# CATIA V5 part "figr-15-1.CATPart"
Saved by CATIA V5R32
Part number: Part1
Bounding box of the stored display mesh (mm): x -92.657 to 112.488, y -68.408 to 38.341, z -24 to 61.972
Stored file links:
  D:\PROJECTS\Project 2022\CATIA V5 6R 2022\Resources\Part Files\c15_catia_v5_6r2022_prt\figr-15-1.CATPart
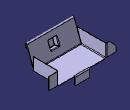
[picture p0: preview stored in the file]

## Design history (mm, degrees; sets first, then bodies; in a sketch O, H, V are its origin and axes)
SheetMetalParameters1: Thickness 1, BendRadius 2, KFactor 0.400515 {= log(min(100,max(20*SheetMetalParameters1.BendRadius,SheetMetalParameters1.Thickness)/SheetMetalParameters1.Thickness))/log(100)/2}, ReliefRadialLength 1, ReliefAxialLength 2, WallPerLength 50, MinimumBendRadius 0
Body1 (main body)
  Sketch1 on xy-plane, origin (0, 0, 0), H (1, 0, 0), V (0, 1, 0)
    line L1 (-62.6567, 37.3409) -> (82.4875, 37.3409)
    line L2 (82.4875, 37.3409) -> (82.4875, -38.1848)
    line L3 (82.4875, -38.1848) -> (-62.6567, -38.1848)
    line L4 (-62.6567, -38.1848) -> (-62.6567, 37.3409)
    horizontal: L1 H, L3 H
    vertical: L2 V, L4 V
  Wall1: Thickness 1, Profile Sketch1, OffsetValue 0
  d_NewWallOnEdge1: KFacteur 0.400515 {= log(min(100,max(20*d_NewWallOnEdge1.Radius,SheetMetalParameters1.Thickness)/SheetMetalParameters1.Thickness))/log(100)/2}, NewWallOnEdge_Length 25, NewWallOnEdge_HeightLimitOffset 0, NewWallOnEdge_WidthOffset1 -50, NewWallOnEdge_WidthOffset2 -50, NewWallOnEdge_Angle 90, NewWallOnEdge_BendRadiusValue 2 {= SheetMetalParameters1.BendRadius}, NewWallOnEdge_BendTable SheetMetalParameters1, NewWallOnEdge_Edge edge [face of Wall1 | face of Wall1], NewWallOnEdge_GapValue 0
  d_NewWallOnEdge2: KFacteur 0.400515 {= log(min(100,max(20*d_NewWallOnEdge2.Radius,SheetMetalParameters1.Thickness)/SheetMetalParameters1.Thickness))/log(100)/2}, NewWallOnEdge_Length 40, NewWallOnEdge_HeightLimitOffset 0, NewWallOnEdge_WidthOffset1 0, NewWallOnEdge_WidthOffset2 0, NewWallOnEdge_Angle 90, NewWallOnEdge_BendRadiusValue 2 {= SheetMetalParameters1.BendRadius}, NewWallOnEdge_BendTable SheetMetalParameters1, NewWallOnEdge_Edge edge [face of Wall1 | face of Wall1], NewWallOnEdge_GapValue 0
  d_NewWallOnEdge3: KFacteur 0.400515 {= log(min(100,max(20*d_NewWallOnEdge3.Radius,SheetMetalParameters1.Thickness)/SheetMetalParameters1.Thickness))/log(100)/2}, NewWallOnEdge_Length 30, NewWallOnEdge_HeightLimitOffset 0, NewWallOnEdge_WidthOffset1 0, NewWallOnEdge_WidthOffset2 0, NewWallOnEdge_Angle 90, NewWallOnEdge_BendRadiusValue 2 {= SheetMetalParameters1.BendRadius}, NewWallOnEdge_BendTable SheetMetalParameters1, NewWallOnEdge_Edge edge [face of d_NewWallOnEdge2 | face of d_NewWallOnEdge2], NewWallOnEdge_GapValue 0
  d_NewWallOnEdge4: KFacteur 0.400515 {= log(min(100,max(20*d_NewWallOnEdge4.Radius,SheetMetalParameters1.Thickness)/SheetMetalParameters1.Thickness))/log(100)/2}, NewWallOnEdge_Length 60, NewWallOnEdge_HeightLimitOffset 0, NewWallOnEdge_WidthOffset1 0, NewWallOnEdge_WidthOffset2 0, NewWallOnEdge_Angle 110, NewWallOnEdge_BendRadiusValue 2 {= SheetMetalParameters1.BendRadius}, NewWallOnEdge_BendTable SheetMetalParameters1, NewWallOnEdge_Edge edge [face of Wall1 | face of Wall1], NewWallOnEdge_GapValue 0
  Flange1: Guide edge [face of d_NewWallOnEdge4 | face of d_NewWallOnEdge4], Angle 90, KFacteur 0.400515 {= log(min(100,max(20*Flange1.Radius,SheetMetalParameters1.Thickness)/SheetMetalParameters1.Thickness))/log(100)/2}, Length 10, Radius 2 {= SheetMetalParameters1.BendRadius}
  d_NewWallOnEdge5: KFacteur 0.400515 {= log(min(100,max(20*d_NewWallOnEdge5.Radius,SheetMetalParameters1.Thickness)/SheetMetalParameters1.Thickness))/log(100)/2}, NewWallOnEdge_Length 40, NewWallOnEdge_HeightLimitOffset 0, NewWallOnEdge_WidthLimit2 face of d_NewWallOnEdge4, NewWallOnEdge_WidthOffset1 0, NewWallOnEdge_WidthOffset2 -2, NewWallOnEdge_Angle 90, NewWallOnEdge_WithBend true, NewWallOnEdge_BendRadiusValue 2 {= SheetMetalParameters1.BendRadius}, NewWallOnEdge_BendTable SheetMetalParameters1, NewWallOnEdge_Edge edge [face of Wall1 | face of Wall1], NewWallOnEdge_GapValue 0
  d_NewWallOnEdge6: KFacteur 0.400515 {= log(min(100,max(20*d_NewWallOnEdge6.Radius,SheetMetalParameters1.Thickness)/SheetMetalParameters1.Thickness))/log(100)/2}, NewWallOnEdge_Length 30, NewWallOnEdge_HeightLimitOffset 0, NewWallOnEdge_WidthOffset1 0, NewWallOnEdge_WidthOffset2 0, NewWallOnEdge_Angle 90, NewWallOnEdge_BendRadiusValue 2 {= SheetMetalParameters1.BendRadius}, NewWallOnEdge_BendTable SheetMetalParameters1, NewWallOnEdge_Edge edge [face of d_NewWallOnEdge5 | face of d_NewWallOnEdge5], NewWallOnEdge_GapValue 0
  Chamfer1: ChamferAngle 45, CornerChamferEdges edge [face of d_NewWallOnEdge6 | face of d_NewWallOnEdge6], ChamferLength1 20, ChamferLength2 0.5, ChamferPropagation 1, ChamferReverse false, ChamferType 1
  Corner1: CornerChamferEdges (edge [face of d_NewWallOnEdge1 | face of d_NewWallOnEdge1]; edge [face of d_NewWallOnEdge1 | face of d_NewWallOnEdge1]), CornerRadius 3
  Sketch2 on face of d_NewWallOnEdge4, origin (8.9154, -38.1848, 1), H (1, 0, 0), V (0, -0.342, 0.9397)
    line L1 (-12.2908, 45.4061) -> (12.3784, 45.4061)
    line L2 (12.3784, 45.4061) -> (12.3784, 21.719)
    line L3 (12.3784, 21.719) -> (-12.2908, 21.719)
    line L4 (-12.2908, 21.719) -> (-12.2908, 45.4061)
    horizontal: L1 H, L3 H
    vertical: L2 V, L4 V
  d_Stamp1: NewRoot_AttribNormalisation "No Standard", Stamp_FilletRadius 1, Stamp_IntersectFilletRadius 2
